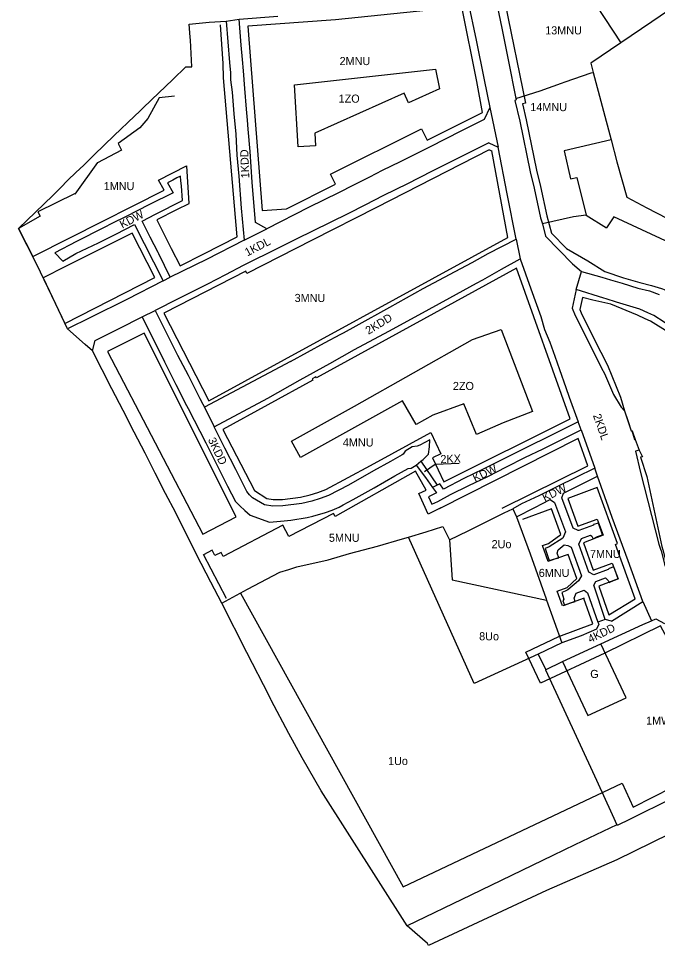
# Model space of a CAD drawing. Extents: x 7422310 to 7423642, y 5546060 to 5546927.
# Drawn here: x 7422506 to 7422901, y 5546060 to 5546632 of the extents above; entities that cross this region are included whole.
import ezdxf

# ---------------------------------------------------------------- set-up
doc = ezdxf.new("R2010")
doc.units = 0
for name, color, linetype in [('linie_rozgraniczajace', 7, 'Continuous'), ('linie_zabudowy_nieprzekraczalne', 7, 'Continuous'), ('oznaczenia_przeznaczen', 7, 'Continuous')]:
    doc.layers.add(name, color=color, linetype=linetype)

msp = doc.modelspace()

# ---------------------------------------------------------------- linework, layer by layer
at = {"layer": 'linie_rozgraniczajace'}
for p, q in [((7422797.53, 5546577.28), (7422793.92, 5546569.87)), ((7422797.53, 5546577.28), (7422802.54, 5546552.81)), ((7422796.9, 5546555.57), (7422802.54, 5546552.81)), ((7422857, 5546510.91), (7422869.61, 5546502.93)), ((7422874.08, 5546509.77), (7422869.61, 5546502.93)), ((7422645.79, 5546495.47), (7422659.79, 5546502.47)), ((7422813.76, 5546496.09), (7422816.13, 5546483.86)), ((7422850.77, 5546464.93), (7422854.07, 5546476.02)), ((7422595.81, 5546470.22), (7422600.15, 5546472.47)), ((7422582.76, 5546448.13), (7422590.7, 5546451.96)), ((7422674.3, 5546420.39), (7422621.17, 5546392.24)), ((7422853.86, 5546378.14), (7422852.11, 5546383.08)), ((7422754.92, 5546358.81), (7422764.98, 5546344.12)), ((7422649.55, 5546325.53), (7422661.33, 5546321.26)), ((7422787.77, 5546221.58), (7422747.32, 5546311.88)), ((7422891.97, 5546272.19), (7422897.22, 5546260.27)), ((7422868.62, 5546261.03), (7422864.26, 5546259.48)), ((7422866.06, 5546246.02), (7422892, 5546257.97)), ((7422900.04, 5546261.52), (7422905.28, 5546258.55))]:
    msp.add_line(p, q, dxfattribs=at)
for points in [[(7422854.6, 5546657.28), (7422863.32, 5546640.22), (7422878.42, 5546617.37)], [(7422808.31, 5546647.6), (7422801.89, 5546641.18), (7422805.03, 5546625.43), (7422808.72, 5546606.77), (7422813.51, 5546583.01), (7422813.68, 5546582.08), (7422812.98, 5546581.79), (7422816.02, 5546568.9), (7422822.48, 5546537.68), (7422824.86, 5546527.61), (7422828.8, 5546509.26), (7422830.09, 5546505.57), (7422831.82, 5546497.81), (7422848.46, 5546480.79), (7422854.07, 5546476.02), (7422866.62, 5546472.44), (7422871.93, 5546470.92), (7422879.12, 5546468.86), (7422888.95, 5546465.8), (7422896.1, 5546464.02), (7422902.1, 5546461.88)], [(7422783.95, 5546643.35), (7422788.98, 5546619.06), (7422794.05, 5546594.45), (7422797.53, 5546577.28)], [(7422913.66, 5546641.25), (7422897.54, 5546630.3), (7422878.42, 5546617.37), (7422859.76, 5546604.84), (7422861.32, 5546598.96), (7422872.4, 5546557.3), (7422875.92, 5546543.85), (7422882.03, 5546521.92), (7422894.46, 5546515.44), (7422913.24, 5546505.76)], [(7422941.03, 5546144.48), (7422875.82, 5546112.55), (7422832.43, 5546093.53), (7422759.62, 5546059.63), (7422758.94, 5546060.8), (7422746.33, 5546071.68), (7422693.36, 5546155.27), (7422681.5, 5546175.59), (7422673.36, 5546190.63), (7422662.49, 5546211.28), (7422662.28, 5546211.69), (7422661.14, 5546213.86), (7422647.46, 5546240.67), (7422631.88, 5546271.02), (7422625.19, 5546284.15), (7422616.31, 5546301.26), (7422603.47, 5546326.92), (7422597.17, 5546338.88), (7422590.88, 5546351.53), (7422584.51, 5546363.83), (7422577.82, 5546376.87), (7422571.06, 5546390.09), (7422563.94, 5546403.56), (7422552.05, 5546426.95), (7422547.59, 5546430.88), (7422536.64, 5546440.52), (7422529.16, 5546456.21), (7422519.95, 5546475.55), (7422517.23, 5546481.24), (7422506.41, 5546502.64), (7422516.8, 5546512.79), (7422527.52, 5546523.03), (7422532.36, 5546527.8), (7422536.92, 5546532.39), (7422541.78, 5546537.16), (7422546.7, 5546541.82), (7422553.06, 5546548.18), (7422565.5, 5546560.03), (7422578.02, 5546572.03), (7422581.32, 5546575.07), (7422583.22, 5546576.87), (7422588.56, 5546582), (7422601.65, 5546594.65), (7422609.66, 5546602.48), (7422613.4, 5546602.45), (7422612.59, 5546618.89), (7422612.48, 5546620.85), (7422611.72, 5546628.83), (7422624.22, 5546630.1), (7422634.54, 5546630.74), (7422642.6, 5546631.86), (7422666.55, 5546633.78)], [(7422634.54, 5546630.74), (7422636.72, 5546605.26), (7422637.26, 5546598.86), (7422637.35, 5546595.87), (7422637.39, 5546594.36), (7422638.28, 5546586.87), (7422639.43, 5546573.45), (7422640.51, 5546560.99), (7422641.28, 5546547.93), (7422642.51, 5546534.99), (7422644, 5546515.08), (7422645.79, 5546495.47), (7422622.43, 5546483.53), (7422600.15, 5546472.47), (7422592.96, 5546486.98), (7422592.59, 5546487.69), (7422587.74, 5546497.16), (7422582.81, 5546507.21), (7422590.89, 5546511.37), (7422607.75, 5546519.9), (7422606.95, 5546529.03), (7422606.7, 5546532.01), (7422606.46, 5546534.87), (7422604.24, 5546533.86), (7422601.79, 5546532.44), (7422598.47, 5546530.81), (7422601.91, 5546524.72), (7422587.33, 5546517.38), (7422572.52, 5546509.88), (7422564.46, 5546505.9), (7422558.8, 5546503.09), (7422553.2, 5546500.22), (7422547.9, 5546497.47), (7422542.27, 5546494.56), (7422528.92, 5546487.65)], [(7422793.92, 5546569.87), (7422779.55, 5546562.65), (7422760.69, 5546553.06), (7422742.06, 5546543.82), (7422731.02, 5546538.35), (7422723.12, 5546534.28), (7422717.74, 5546531.61), (7422712.88, 5546529.11), (7422704.49, 5546524.81), (7422685.39, 5546515.49), (7422659.79, 5546502.47), (7422652.68, 5546506.31), (7422650.74, 5546531.21), (7422649.36, 5546550.25), (7422648.29, 5546563.94), (7422647.73, 5546569.55), (7422647.22, 5546576.28), (7422646.13, 5546589.03), (7422645.28, 5546600.01), (7422644.64, 5546606.95), (7422644, 5546615.88), (7422642.6, 5546631.86)], [(7422676.83, 5546591.38), (7422763.91, 5546601.13), (7422766.42, 5546588.84), (7422747.23, 5546580.22), (7422744.53, 5546586.25), (7422689.39, 5546561.5), (7422689.9, 5546553.67), (7422679.11, 5546552.97), (7422676.83, 5546591.38)], [(7422813.51, 5546583.01), (7422828.59, 5546587.75), (7422841.8, 5546592.31), (7422844.09, 5546593.24), (7422860.07, 5546598.81), (7422861.32, 5546598.96)], [(7422796.9, 5546555.57), (7422774.17, 5546544.17), (7422763.16, 5546538.71), (7422752.99, 5546533.48), (7422747.09, 5546530.45), (7422731.37, 5546522.77), (7422720.72, 5546517.21), (7422709.76, 5546511.74), (7422688.4, 5546501.18), (7422677.77, 5546495.95), (7422667.14, 5546490.73), (7422645.22, 5546479.67), (7422634.31, 5546474.05), (7422623.09, 5546468.29), (7422604.9, 5546459.16), (7422590.7, 5546451.96), (7422604.61, 5546424.3), (7422611.08, 5546411.96), (7422618.45, 5546397.65), (7422620.25, 5546394.08)], [(7422872.4, 5546557.3), (7422843.35, 5546550.59), (7422847.39, 5546533.3), (7422851.22, 5546534.19), (7422857, 5546510.91)], [(7422674.3, 5546420.39), (7422695.31, 5546431.87), (7422705.41, 5546437.3), (7422707.03, 5546438.16), (7422714.92, 5546442.51), (7422735.75, 5546454.1), (7422756.31, 5546465.54), (7422776.08, 5546476.09), (7422786.49, 5546481.7), (7422796.34, 5546487.1), (7422813.76, 5546496.09), (7422808.18, 5546524.09), (7422802.54, 5546552.81)], [(7422857, 5546510.91), (7422849.08, 5546509.73), (7422830.09, 5546505.57)], [(7422938.84, 5546480.42), (7422928.13, 5546484.56), (7422914.39, 5546490.97), (7422874.08, 5546509.77)], [(7422528.92, 5546487.65), (7422533.66, 5546482.5), (7422541.85, 5546487.09), (7422555.84, 5546493.79), (7422566.48, 5546499.08), (7422578.09, 5546505.03), (7422595.81, 5546470.22), (7422573.37, 5546458.84), (7422550.92, 5546447.68), (7422536.64, 5546440.52)], [(7422661.33, 5546321.26), (7422670.36, 5546321.98), (7422674.53, 5546322.42), (7422684.68, 5546323.97), (7422688.23, 5546324.87), (7422695.92, 5546327.15), (7422700.1, 5546328.57), (7422704.32, 5546330.51), (7422706.9, 5546331.8), (7422713.15, 5546335.1), (7422726.01, 5546342.39), (7422738.89, 5546349.73), (7422747.06, 5546354.3), (7422748.95, 5546354.48), (7422752.03, 5546356.29), (7422754.92, 5546358.81), (7422756.23, 5546359.95), (7422759.68, 5546363.24), (7422760.14, 5546367.7), (7422760.35, 5546372.12), (7422754.2, 5546368.72), (7422752.57, 5546368.12), (7422749.5, 5546367.65), (7422745.19, 5546365.04), (7422744.05, 5546363.21), (7422743.33, 5546362.72), (7422736.1, 5546358.63), (7422725.65, 5546352.79), (7422710.24, 5546343.93), (7422697.74, 5546337.69), (7422692.59, 5546335.73), (7422687.47, 5546334.13), (7422681.33, 5546332.68), (7422669.73, 5546331.25), (7422663.4, 5546331.06), (7422658.27, 5546331.9), (7422650.97, 5546336.23), (7422649.03, 5546338.05), (7422647.48, 5546340.12), (7422640.53, 5546353.67), (7422633.89, 5546366.88), (7422627.25, 5546380.1), (7422660.36, 5546397.79), (7422680.34, 5546409.19), (7422698.61, 5546419.28), (7422713.89, 5546427.79), (7422735.15, 5546439.26), (7422753.71, 5546449.33), (7422772.75, 5546459.7), (7422789.26, 5546468.76), (7422793.24, 5546470.96), (7422804.72, 5546477.54), (7422816.13, 5546483.86), (7422822.81, 5546465.28), (7422828.87, 5546448.19), (7422831.32, 5546440.29), (7422834.58, 5546432.29), (7422837.7, 5546423.76), (7422840.6, 5546415.4), (7422844.48, 5546404.34), (7422846.55, 5546398.47), (7422852.11, 5546383.08), (7422802.79, 5546358.57), (7422793.35, 5546353.92), (7422781.45, 5546348.12), (7422768.91, 5546341.45), (7422766.53, 5546344.91)], [(7422942.84, 5546418.27), (7422938.07, 5546422.01), (7422924.52, 5546431.41), (7422920.21, 5546434.18), (7422910.98, 5546440.54), (7422905.16, 5546444.71), (7422898.7, 5546448.79), (7422895.11, 5546450.46), (7422890.01, 5546452.75), (7422875.8, 5546457.17), (7422869.23, 5546459.14), (7422867.87, 5546459.46), (7422850.77, 5546464.93), (7422848.28, 5546453.48), (7422850.16, 5546448.92), (7422858.34, 5546432.53), (7422866.53, 5546416.28), (7422868.25, 5546412.95), (7422873.93, 5546400.01), (7422878.61, 5546392.2), (7422880.68, 5546389.97), (7422882.72, 5546383.91)], [(7422552.05, 5546426.95), (7422553.77, 5546433.37), (7422568.54, 5546440.88), (7422582.76, 5546448.13), (7422596.46, 5546420.19), (7422603.58, 5546406.3), (7422610.15, 5546393.33), (7422611.1, 5546391.47), (7422621.99, 5546370.09), (7422623.04, 5546368.02), (7422629.41, 5546355.44), (7422635.51, 5546343.5), (7422640.38, 5546333.92), (7422643.03, 5546331.26), (7422646.16, 5546328.39), (7422649.55, 5546325.53)], [(7422804.54, 5546440.1), (7422823.83, 5546389.55), (7422805.74, 5546382.63), (7422789.23, 5546375.4), (7422781.42, 5546394.19), (7422762.18, 5546387.29), (7422751.88, 5546381.45), (7422743.58, 5546396.08), (7422680.56, 5546361.21), (7422675.02, 5546371.23), (7422713.88, 5546392.74), (7422786.75, 5546434), (7422804.54, 5546440.1)], [(7422620.25, 5546394.08), (7422621.17, 5546392.24), (7422627.25, 5546380.1)], [(7422882.72, 5546383.91), (7422884.75, 5546377.58), (7422885.13, 5546377.71), (7422886.89, 5546372.24), (7422887.19, 5546372.34), (7422887.25, 5546372.18), (7422889.62, 5546365.57), (7422887.5, 5546364.99), (7422890.5, 5546351.82), (7422901.88, 5546307.51), (7422902.98, 5546303.83), (7422903.21, 5546303.56), (7422905.4, 5546295.31), (7422909.08, 5546284.94), (7422912.92, 5546277.1)], [(7422765.3, 5546334.01), (7422773.14, 5546338.17), (7422784.57, 5546343.78), (7422796.14, 5546349.42), (7422807.7, 5546355.38), (7422819.11, 5546361.05), (7422830.37, 5546366.52), (7422841.88, 5546372.21), (7422853.86, 5546378.14), (7422862.28, 5546354.57), (7422850.57, 5546348.73), (7422839.22, 5546343.13), (7422827.75, 5546337.45), (7422816.96, 5546332.41), (7422811.58, 5546329.46)], [(7422752.03, 5546356.29), (7422757.71, 5546348.85), (7422762.04, 5546342.64), (7422764.45, 5546339.2)], [(7422848.89, 5546317.45), (7422841.89, 5546336.23), (7422843.05, 5546339.13), (7422852.34, 5546343.92), (7422864.01, 5546349.61), (7422862.28, 5546354.57)], [(7422872.54, 5546260.09), (7422891.97, 5546272.19), (7422882.98, 5546297.23), (7422873.12, 5546324.12), (7422864.01, 5546349.61)], [(7422766.53, 5546344.91), (7422764.98, 5546344.12), (7422762.04, 5546342.64)], [(7422764.45, 5546339.2), (7422759.53, 5546336.72), (7422761.56, 5546332.22), (7422765.3, 5546334.01)], [(7422813.96, 5546324.56), (7422825.26, 5546330.17), (7422834.69, 5546335.08), (7422837.43, 5546333.37), (7422844.23, 5546315.16)], [(7422631.88, 5546271.02), (7422647.89, 5546279.7), (7422667.84, 5546290.24), (7422673.34, 5546291.96), (7422678.37, 5546293.53), (7422697.56, 5546297.98), (7422710.76, 5546301.8), (7422728.1, 5546306.39), (7422743.62, 5546310.79), (7422747.32, 5546311.88), (7422758.07, 5546315.27), (7422768.46, 5546318.39), (7422772.64, 5546310.24), (7422784.03, 5546315.91), (7422794.44, 5546320.9), (7422806.24, 5546326.86), (7422811.58, 5546329.46), (7422813.96, 5546324.56), (7422822.35, 5546301.52), (7422832.17, 5546273.77), (7422832.44, 5546273.02), (7422841.91, 5546246.64), (7422827.25, 5546239.7), (7422831.78, 5546230.34), (7422831.94, 5546230), (7422863.31, 5546161.73), (7422873.09, 5546140.53), (7422875.95, 5546134.22), (7422849.92, 5546121.84), (7422836.28, 5546115.13), (7422810.75, 5546102.81), (7422785.71, 5546090.74), (7422746.33, 5546071.68)], [(7422852.42, 5546307.58), (7422854, 5546311.04), (7422859.57, 5546313.08), (7422860.49, 5546312.5), (7422861.28, 5546310.86), (7422863.98, 5546312.26), (7422867, 5546313.36), (7422864.55, 5546320.6), (7422861.44, 5546319.8), (7422861.57, 5546319.38), (7422852.34, 5546315.97), (7422852.01, 5546315.94), (7422848.89, 5546317.45)], [(7422844.23, 5546315.16), (7422842.54, 5546311.37), (7422834.16, 5546305.86), (7422831.61, 5546304.94), (7422834.16, 5546297.45), (7422836.84, 5546298.33), (7422840.03, 5546299.18), (7422839.03, 5546302.08), (7422839.64, 5546304.13), (7422843.45, 5546307.13), (7422845.69, 5546306.72), (7422847.69, 5546305.62)], [(7422772.64, 5546310.24), (7422774.15, 5546285.62), (7422832.44, 5546273.02)], [(7422858.68, 5546290.17), (7422852.42, 5546307.58)], [(7422847.69, 5546305.62), (7422854.07, 5546288.06)], [(7422861.68, 5546282.16), (7422863.03, 5546284.55), (7422868.99, 5546286.72), (7422870.61, 5546285.12), (7422871.21, 5546283.94), (7422873.88, 5546285.18), (7422876.66, 5546286.22), (7422873.99, 5546293.47), (7422871.14, 5546292.5), (7422870.56, 5546291.88), (7422861.61, 5546288.69), (7422858.68, 5546290.17)], [(7422854.07, 5546288.06), (7422852.21, 5546284.84), (7422845.73, 5546279.35), (7422844.02, 5546278.56), (7422842.04, 5546277.8), (7422843.08, 5546273.55), (7422842.55, 5546272.64), (7422843.64, 5546269.88), (7422846.84, 5546271.05), (7422850.21, 5546272.13), (7422849.54, 5546274.16), (7422850.76, 5546277.36), (7422855.81, 5546279.14), (7422857.89, 5546277.41)], [(7422872.54, 5546260.09), (7422868.62, 5546261.03), (7422861.68, 5546282.16)], [(7422857.89, 5546277.41), (7422864.26, 5546259.48), (7422864.76, 5546258.08), (7422863.35, 5546255.02), (7422853.92, 5546251.03), (7422841.91, 5546246.64)], [(7422892, 5546257.97), (7422897.22, 5546260.27), (7422900.04, 5546261.52)], [(7422831.94, 5546230), (7422842.42, 5546235.07), (7422866.06, 5546246.02)], [(7422842.42, 5546235.07), (7422858.04, 5546201.67), (7422881.71, 5546212.65), (7422866.06, 5546246.02)], [(7422827.25, 5546239.7), (7422787.77, 5546221.58)], [(7422875.95, 5546134.22), (7422876.79, 5546134.17), (7422884.01, 5546137.67), (7422910.51, 5546150.81), (7422916.79, 5546154.09), (7422953.34, 5546172.11)]]:
    msp.add_lwpolyline(points, dxfattribs=at)
at = {"layer": 'linie_zabudowy_nieprzekraczalne'}
for p, q in [((7422807.04, 5546641.5), (7422819.43, 5546580.13)), ((7422819.43, 5546580.13), (7422817.6, 5546579.63)), ((7422538.53, 5546497.03), (7422596.37, 5546526.39)), ((7422611.62, 5546517.92), (7422603.91, 5546514.04)), ((7422519.7, 5546510.24), (7422506.41, 5546502.64)), ((7422515.15, 5546485.35), (7422538.53, 5546497.03)), ((7422535.31, 5546479.11), (7422521.54, 5546472.2)), ((7422535.03, 5546443.89), (7422590.58, 5546472.29)), ((7422620.17, 5546313.76), (7422640.88, 5546324.55)), ((7422669.66, 5546319.33), (7422632.79, 5546299.91)), ((7422625.96, 5546303.93), (7422620.59, 5546301.03)), ((7422627.67, 5546300.5), (7422625.96, 5546303.93)), ((7422631.57, 5546302.33), (7422627.67, 5546300.5)), ((7422632.79, 5546299.91), (7422631.57, 5546302.33)), ((7422643.51, 5546277.33), (7422743.99, 5546095.77)), ((7422870.93, 5546263.88), (7422887.27, 5546273.78)), ((7422743.99, 5546095.77), (7422879.23, 5546159.93)), ((7422879.23, 5546159.93), (7422885.92, 5546145))]:
    msp.add_line(p, q, dxfattribs=at)
for points in [[(7422780.16, 5546639.51), (7422702.06, 5546631.59), (7422648.09, 5546627.53)], [(7422789.38, 5546593.39), (7422780.16, 5546639.51)], [(7422633.03, 5546595.73), (7422632.8, 5546604.62), (7422631.07, 5546628.54), (7422631.07, 5546628.54)], [(7422648.09, 5546627.53), (7422656.9, 5546513.66), (7422671.8, 5546514.81), (7422702.11, 5546529.95)], [(7422641.53, 5546497.45), (7422633.03, 5546595.73)], [(7422699, 5546536.19), (7422755.19, 5546564.26), (7422758.71, 5546557.21), (7422792.92, 5546574.3), (7422789.38, 5546593.39)], [(7422593.28, 5546583.4), (7422586.16, 5546570.56), (7422581.31, 5546564.83), (7422567.92, 5546555.11), (7422570.07, 5546551.05)], [(7422602.82, 5546584.45), (7422593.28, 5546583.4)], [(7422817.6, 5546579.63), (7422819.93, 5546569.76), (7422826.39, 5546538.55), (7422828.76, 5546528.49), (7422832.66, 5546510.34), (7422835.47, 5546499.79), (7422835.47, 5546499.79), (7422844.72, 5546490.18), (7422857.98, 5546482.57), (7422868.51, 5546476.06), (7422868.51, 5546476.06), (7422880.09, 5546472.18), (7422890.18, 5546469.32), (7422897.29, 5546467.43), (7422903.49, 5546465.63), (7422905.82, 5546464.74), (7422917.06, 5546456.03), (7422927.41, 5546447.65), (7422940.37, 5546437.61)], [(7422570.07, 5546551.05), (7422555.27, 5546543.19)], [(7422646.74, 5546476.19), (7422596.6, 5546450.59), (7422596.17, 5546450.37), (7422623.9, 5546396.07), (7422808.53, 5546496.99), (7422798.77, 5546550.68)], [(7422797.15, 5546551.2), (7422727.42, 5546515.6), (7422687.76, 5546495.35), (7422647.46, 5546474.77), (7422646.74, 5546476.19)], [(7422797.15, 5546551.2), (7422798.77, 5546550.68), (7422798.77, 5546550.68)], [(7422555.2, 5546543.32), (7422541.09, 5546523.87)], [(7422596.37, 5546526.39), (7422592.93, 5546532.49), (7422610.16, 5546541.24)], [(7422610.16, 5546541.24), (7422611.67, 5546517.95)], [(7422702.11, 5546529.95), (7422699, 5546536.19)], [(7422540.9, 5546524.08), (7422518.41, 5546512.81), (7422519.7, 5546510.24)], [(7422603.91, 5546514.04), (7422591.76, 5546507.92), (7422600.71, 5546490.15), (7422606.13, 5546479.63), (7422620.78, 5546486.94), (7422641.53, 5546497.45)], [(7422506.41, 5546502.64), (7422515.15, 5546485.35)], [(7422590.58, 5546472.29), (7422576.55, 5546499.65), (7422535.31, 5546479.11)], [(7422813.96, 5546478.09), (7422690.51, 5546410.26), (7422690.11, 5546411), (7422687.69, 5546409.67), (7422688.09, 5546408.94), (7422632.58, 5546378.41)], [(7422847.14, 5546385.07), (7422813.96, 5546478.09)], [(7422521.54, 5546472.2), (7422535.03, 5546443.89)], [(7422896.78, 5546445.27), (7422893.45, 5546446.82), (7422888.59, 5546449), (7422872.26, 5546455.79), (7422872.26, 5546455.79), (7422861.17, 5546458.4), (7422854.71, 5546460.03), (7422852.99, 5546452.56), (7422853.8, 5546450.58), (7422861.92, 5546434.32), (7422870.09, 5546418.1), (7422878.26, 5546398.49), (7422878.26, 5546398.49), (7422880.68, 5546389.97), (7422880.68, 5546389.97)], [(7422942.78, 5546414.42), (7422941.94, 5546415.53), (7422937.13, 5546420.13), (7422896.78, 5546445.27)], [(7422640.88, 5546324.55), (7422583.98, 5546438.01), (7422561.42, 5546426.7), (7422620.17, 5546313.76)], [(7422880.68, 5546389.97), (7422880.68, 5546389.97), (7422884.75, 5546377.58), (7422885.29, 5546377.56), (7422887.25, 5546372.18), (7422889.62, 5546365.57), (7422891.7, 5546361.6), (7422890.48, 5546361.27)], [(7422769.1, 5546346.12), (7422847.14, 5546385.07)], [(7422632.58, 5546378.41), (7422652.03, 5546340.72), (7422659.66, 5546335.72), (7422663.66, 5546335.07), (7422669.42, 5546335.24), (7422680.62, 5546336.62), (7422686.42, 5546337.99), (7422691.28, 5546339.51), (7422696.13, 5546341.36), (7422723.68, 5546356.27), (7422761.05, 5546376.5)], [(7422761.05, 5546376.5), (7422767.24, 5546363.39)], [(7422851.94, 5546372.95), (7422766.27, 5546329.45)], [(7422805.01, 5546329.8), (7422805.01, 5546329.8), (7422858.01, 5546355.99), (7422851.94, 5546372.95)], [(7422767.24, 5546363.39), (7422762.09, 5546360.96)], [(7422762.09, 5546360.96), (7422769.1, 5546346.12)], [(7422890.48, 5546361.27), (7422894.4, 5546349.33), (7422903.76, 5546306.15), (7422903.76, 5546306.15), (7422904.38, 5546303.97), (7422909.15, 5546285.59), (7422913.13, 5546277.45)], [(7422758.07, 5546341.03), (7422751.48, 5546352.67), (7422701.91, 5546324.67), (7422700.92, 5546326.42), (7422673.29, 5546312.24), (7422669.66, 5546319.33)], [(7422876.29, 5546307.89), (7422863.85, 5546342.5), (7422845.72, 5546335.86), (7422851.73, 5546318.7)], [(7422753.66, 5546338.79), (7422758.07, 5546341.03)], [(7422759.34, 5546326.19), (7422753.66, 5546338.79)], [(7422767.23, 5546329.95), (7422759.34, 5546326.19)], [(7422835.57, 5546329.38), (7422817.72, 5546322.91)], [(7422841.34, 5546313.45), (7422835.57, 5546329.38)], [(7422851.72, 5546318.7), (7422863.74, 5546322.93), (7422867.44, 5546313.14), (7422855.28, 5546308.41)], [(7422833.43, 5546296.87), (7422830.07, 5546306.72), (7422833.61, 5546307.94), (7422841.34, 5546313.45)], [(7422855.33, 5546308.43), (7422861.26, 5546291.48)], [(7422875.09, 5546307.45), (7422876.29, 5546307.89)], [(7422887.27, 5546273.78), (7422875.09, 5546307.45)], [(7422620.46, 5546301.29), (7422634.6, 5546274.11)], [(7422845.77, 5546301.23), (7422833.39, 5546296.86)], [(7422851.15, 5546286.38), (7422845.77, 5546301.23)], [(7422861.26, 5546291.48), (7422873.12, 5546295.81), (7422876.66, 5546286.22), (7422864.71, 5546281.65)], [(7422842.43, 5546269.54), (7422839.08, 5546278.56), (7422845.17, 5546280.82), (7422851.15, 5546286.38)], [(7422864.71, 5546281.65), (7422870.93, 5546263.88)], [(7422819.61, 5546240.79), (7422840.18, 5546250.42), (7422861, 5546258.39), (7422855.58, 5546274.1)], [(7422855.64, 5546274.12), (7422842.46, 5546269.55)], [(7422885.92, 5546145), (7422946.82, 5546175.98), (7422902.8, 5546257.21), (7422868.43, 5546240.14), (7422828.79, 5546221.69), (7422819.61, 5546240.79)]]:
    msp.add_lwpolyline(points, dxfattribs=at)
at = {"layer": 'oznaczenia_przeznaczen'}
msp.add_lwpolyline([(7422757.06, 5546352.43), (7422763.78, 5546357.07), (7422778.53, 5546357.67)], dxfattribs=at)

# ---------------------------------------------------------------- texts
for s, p in [('13MNU', (7422831.67, 5546622.53)), ('2MNU', (7422704.68, 5546603.57)), ('1ZO', (7422704.09, 5546580.34)), ('14MNU', (7422822.48, 5546575.13)), ('1MNU', (7422559.01, 5546526.32)), ('3MNU', (7422676.91, 5546457.19)), ('2ZO', (7422774.64, 5546402.81)), ('4MNU', (7422706.71, 5546367.92)), ('5MNU', (7422698.11, 5546309.02)), ('2Uo', (7422798.55, 5546305.07)), ('7MNU', (7422859.33, 5546299.04)), ('6MNU', (7422827.71, 5546287.32)), ('8Uo', (7422790.88, 5546248.16)), ('G', (7422859.48, 5546224.89)), ('1MW', (7422893.98, 5546196.07)), ('1Uo', (7422734.61, 5546171.1))]:
    msp.add_text(s, height=5, dxfattribs=at).set_placement(p)
for s, rotation, p in [('1KDD', 92.308, (7422648.94, 5546533.73)), ('KDW', 27.4094, (7422570.48, 5546502.5)), ('1KDL', 27.4325, (7422647.71, 5546485.3)), ('2KDD', 31.2653, (7422722.51, 5546436.9)), ('2KDL', 289.2674, (7422861.1, 5546387.12)), ('3KDD', 295.5066, (7422623.24, 5546372.07)), ('2KX', 2.1271, (7422767.05, 5546357.58)), ('KDW', 26.24, (7422788.45, 5546345.76)), ('KDW', 26.24, (7422831.4, 5546333.73)), ('4KDD', 26.24, (7422859.52, 5546246.38))]:
    msp.add_text(s, height=5, rotation=rotation, dxfattribs=at).set_placement(p)

doc.saveas('drawing.dxf')
